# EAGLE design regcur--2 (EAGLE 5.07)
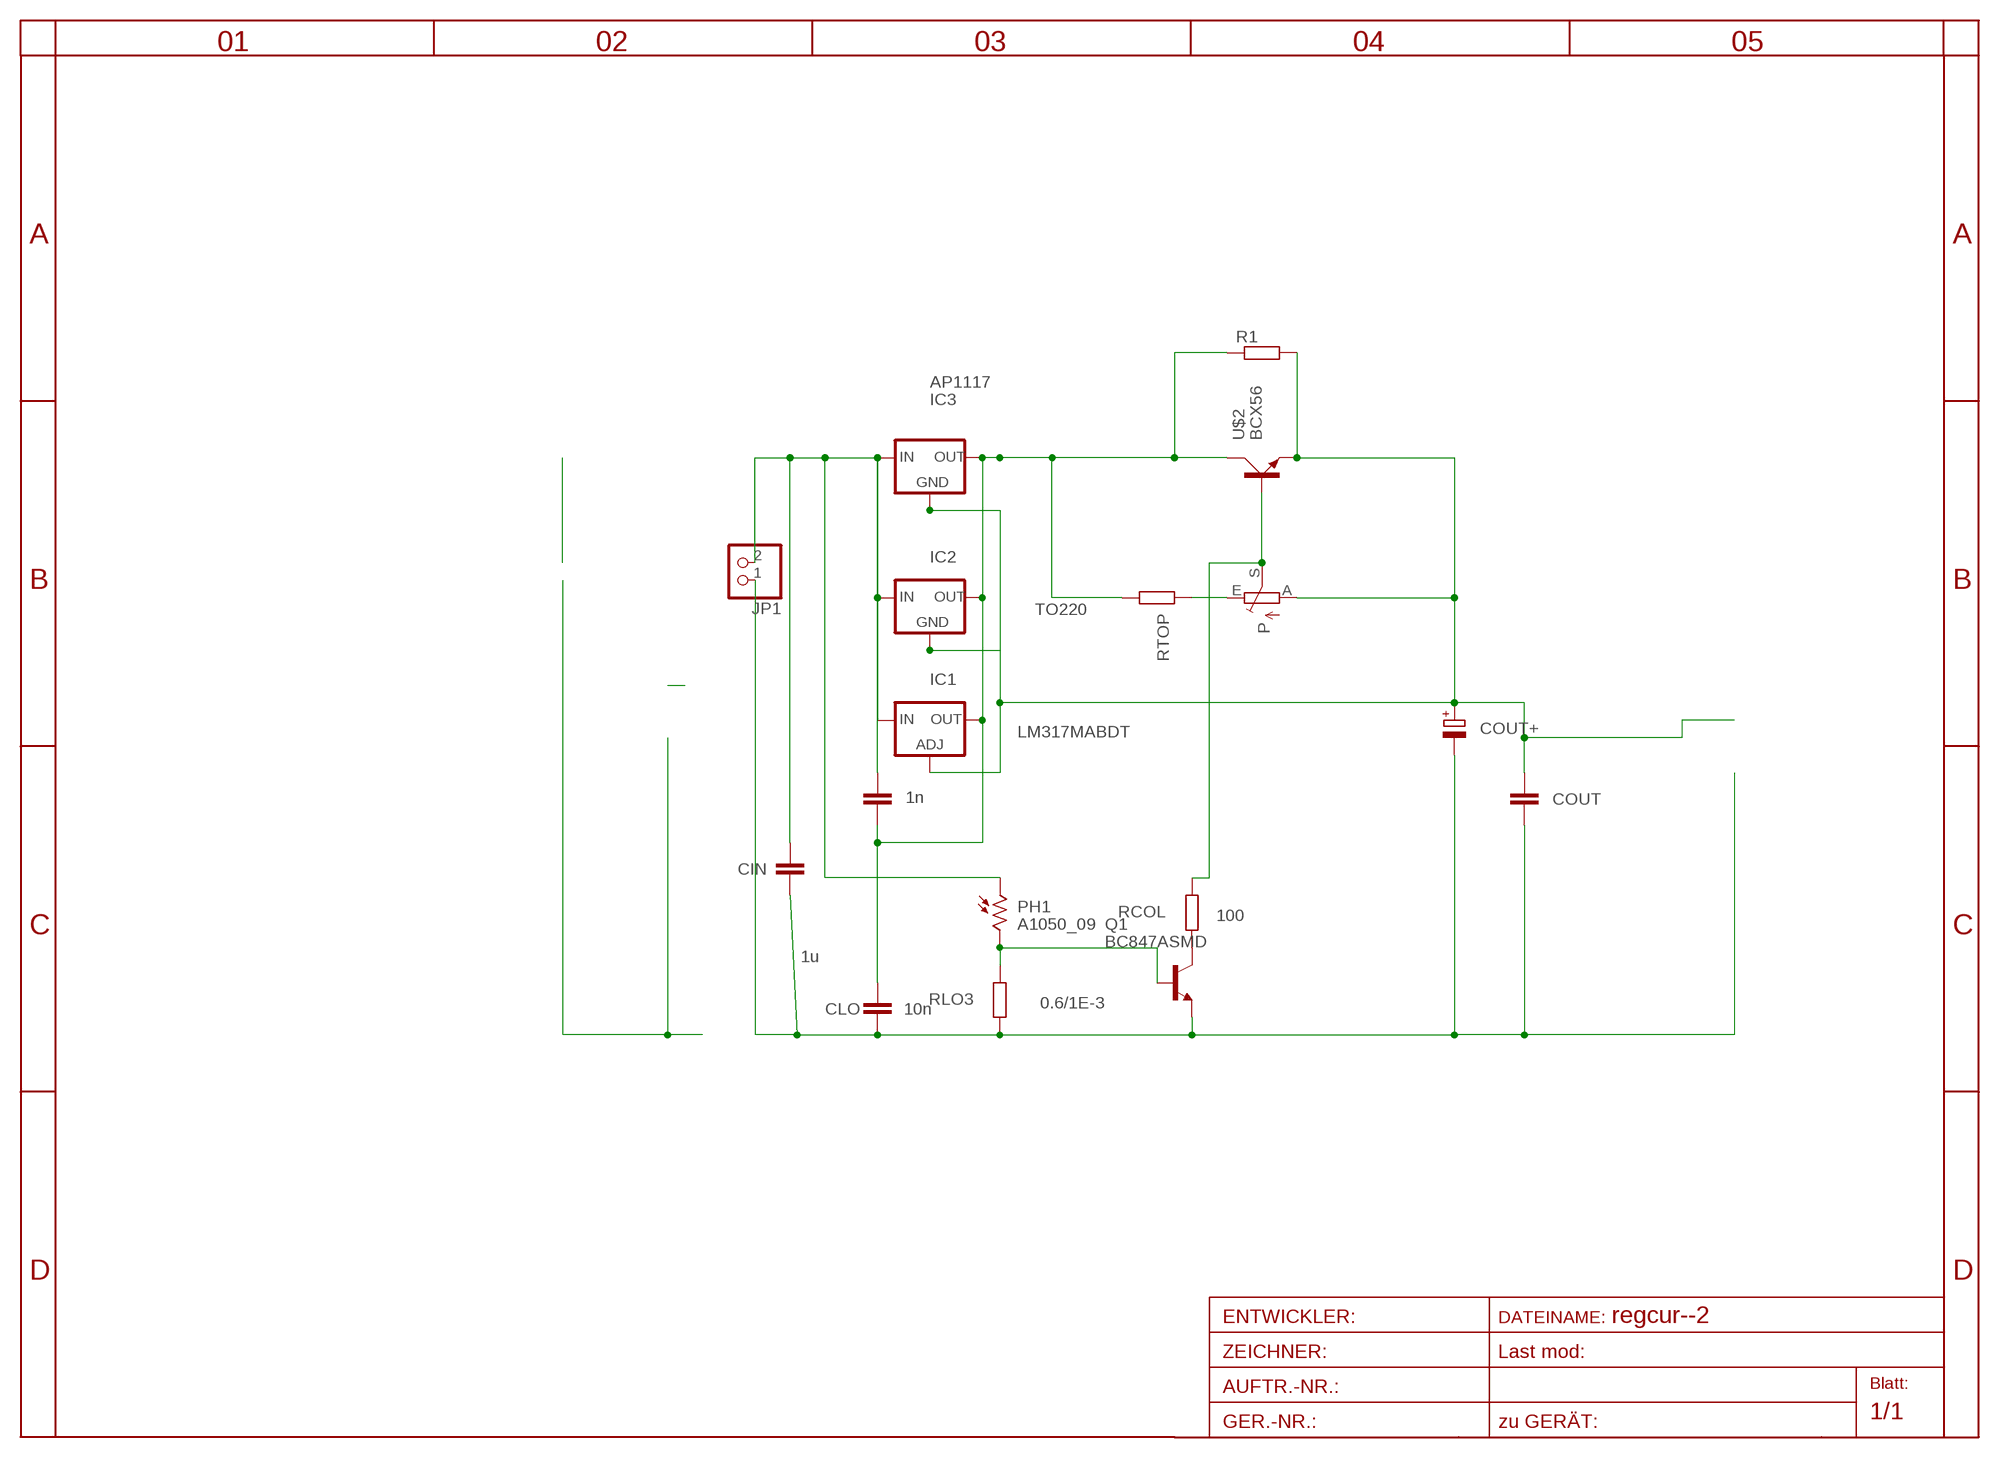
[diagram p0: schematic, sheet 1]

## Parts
CHI  1n  C-EUC0805  [C0805]
CIN  1u  C-EUC1206  [C1206]
CLO  10n  C-EUC0805  [C0805]
COUT  C-EUC1206  [C1206]
COUT+  CPOL-EUE7.5-16  [E7,5-16]
IC1  LM317MABDT  [DPACK]
IC2  TO220  78XXS  [78XXS]
IC3  AP1117  [SOT223]
JP1  PINHD-1X2STR  [1X02]
P  TRIM_EU-RAND160  [RANDL]
PH1  A1050_09  [T0-46-A10XX]
Q1  BC847ASMD  [SOT23]
R1  R-EU_R1210  [R1210]
RCOL  100  R-EU_R0805  [R0805]
RLO3  0.6/1E-3  R-EU_R0805  [R0805]
RTOP  R-EU_R0805  [R0805]
U$2  BCX56  [SOT223]

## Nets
GND: CIN.2 CLO.2 COUT+.- COUT.2 JP1.1 Q1.2(E) RLO3.1
IN: CHI.1 CIN.1 IC1.3(IN) IC2.IN IC3.3(IN) JP1.2 PH1.1
N$3: Q1.3(C) RCOL.1
N$4: P.E RTOP.1
N$5: P.S RCOL.2 U$2.1(B)
N$6: PH1.2 Q1.1(B) RLO3.2
OUT: COUT+.+ COUT.1 IC1.1(ADJ) IC2.GND IC3.1(GND) P.A R1.2 U$2.3(E)
OUT1: CHI.2 CLO.1 IC1.4(OUT) IC2.OUT IC3.2(OUT) IC3.4(TAB) R1.1 RTOP.2 U$2.2(C)

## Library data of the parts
CHI CIN CLO COUT = rcl:C-EU: CAPACITOR, European symbol
COUT+ = rcl:CPOL-EU: POLARIZED CAPACITOR, European symbol
IC1 = v-reg:LM317?*: 500 mA Adjustable Output Positive Voltage Regulator Source: http://www.onsemi.co.jp .. LM317M-D.PDF
IC2 = v-reg:78XXS: VOLTAGE REGULATOR
IC3 = v-reg:AP1117
JP1 = pinhead:PINHD-1X2: PIN HEADER
P = pot:TRIM_EU-: POTENTIOMETER
PH1 = photo-elements:A10: Sensor Robust Light Sensing Applications
Q1 = transistor-npn:BC847*: NPN Transistor
R1 RCOL RLO3 RTOP = rcl:R-EU_: RESISTOR, European symbol
U$2 = transistor-power:BCX56

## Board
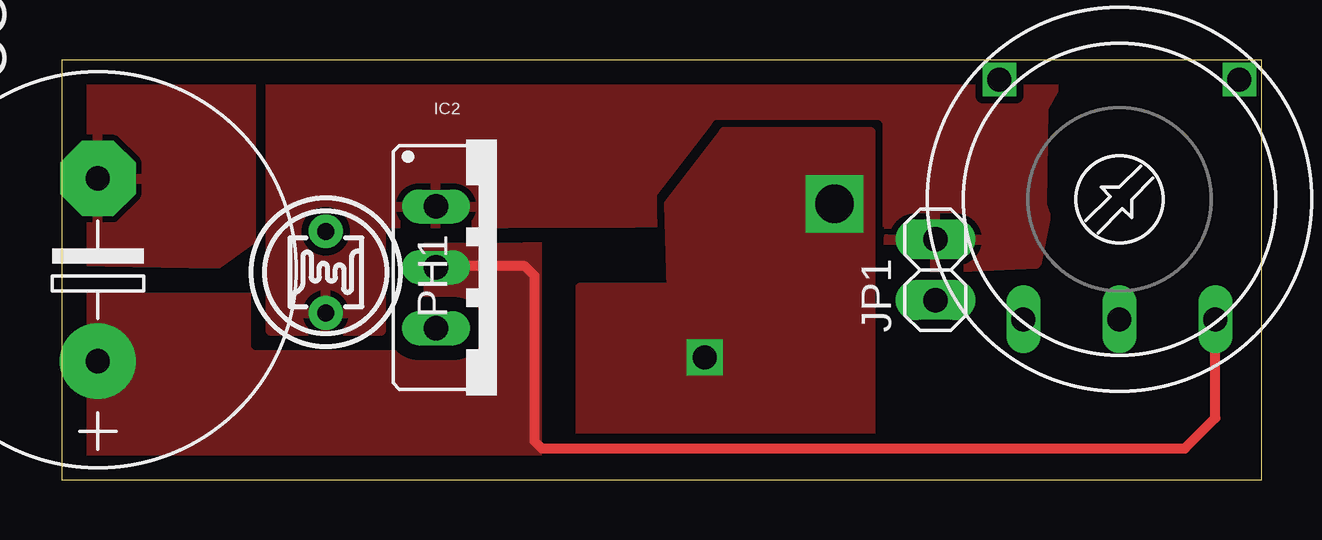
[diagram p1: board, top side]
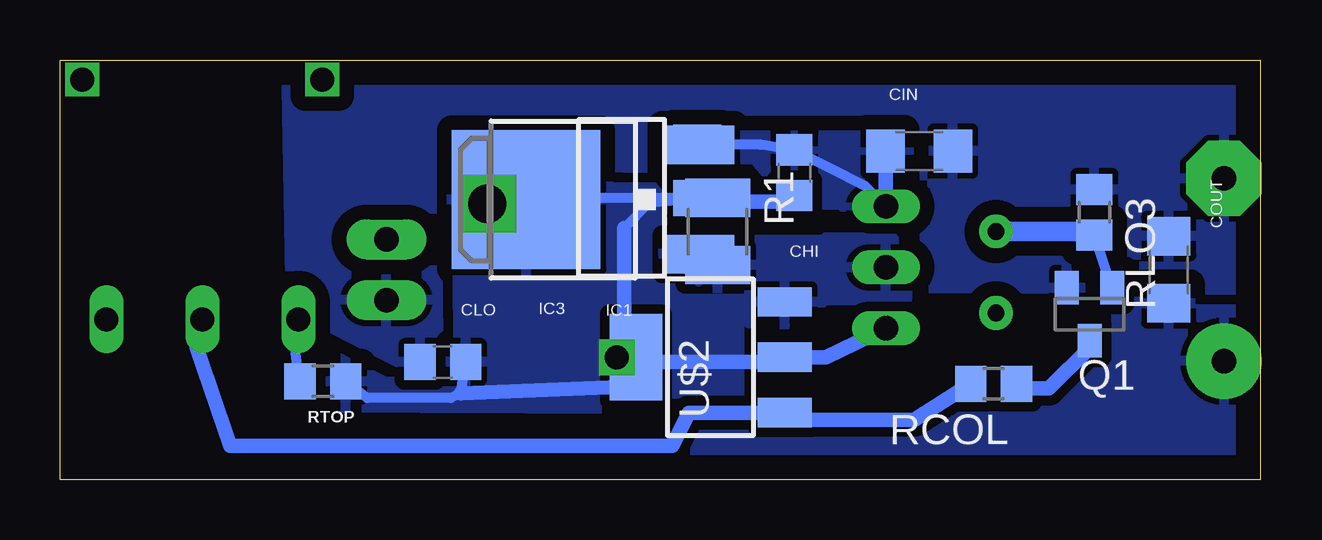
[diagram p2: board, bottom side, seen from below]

Size 50 x 17.5 mm. Coordinates in mm from the lower left corner, seen from the top.
Outline: 0,0 50,0 50,17.5 0,17.5 0,0
Copper layers (1*16): Top 0.035mm / dielectric 1.5mm / Bottom 0.035mm
Design rules "default *": minimum track width 10mil, minimum drill 20mil, track to track 8mil, track to pad 8mil, pad to pad 8mil, via to via 8mil, smd to smd 8mil, copper to edge 40mil, drill to drill 8mil, minimum pad ring 8mil, minimum via ring 8mil, stop-mask expansion 8mil, vias tented up to drill 0mil, thermal gap 10mil

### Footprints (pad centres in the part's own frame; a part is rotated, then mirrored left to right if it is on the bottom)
C0805 = smd 1.3 x 1.5: 1 -0.95,0; 2 0.95,0
C1206 = smd 1.6 x 1.8: 1 -1.4,0; 2 1.4,0
E7,5-16 = drill 1.016 pad 3.15 round: + -3.81,0 | drill 1.016 pad 3.15 octagon: - 3.81,0
DPACK = smd 1.6 x 3: 1 -2.28,-4.8; 3 2.28,-4.8 | smd 5.8 x 6.2: 4 0,2.38
78XXS = drill 1.016 long: GND 0,-2.54; IN -2.54,-2.54; OUT 2.54,-2.54
SOT223 = smd 1.5 x 2: 1 -2.3,-3.15; 2 0,-3.15; 3 2.3,-3.15 | smd 3.8 x 2: 4 0,3.15
1X02 = drill 1.016 pad 1.676 long: 1 -1.27,0; 2 1.27,0
RANDL = drill 1 long: A -4,5; E 4,5; S 0,5 | drill 1 square: P$1 -5,-5; P$2 5,-5
T0-46-A10XX = drill 0.7 pad 1.4 round: 1 -1.7,0; 2 1.7,0
SOT23 = smd 1 x 1.4: 1 -0.95,-1.1; 2 0.95,-1.1; 3 0,1.1
R1210 = smd 1.6 x 2.7: 1 -1.4,0; 2 1.4,0
R0805 = smd 1.3 x 1.5: 1 -0.95,0; 2 0.95,0
SOT223' = smd 1.219 x 2.235: 1 -2.311,-3.099; 2 0,-3.099; 3 2.311,-3.099 | smd 3.6 x 2.2: 4 0,3.099

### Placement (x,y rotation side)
CHI  19.4,12.8 270 bottom
CIN  14.2,13.7 0 bottom
CLO  34.05,4.9 180 bottom
COUT  3.8,8.75 90 bottom
COUT+  1.5,8.75 90 top
IC1  28.2,11.68 90 bottom
IC2  18.13,8.85 270 top
IC3  26.6,11.75 90 bottom
JP1  36.4,8.75 90 top
P  44.07,11.68 180 top
PH1  11,8.65 90 top
Q1  7.1,6.9 180 bottom
R1  22.6,10.35 270 bottom
RCOL  11.1,4 180 bottom
RLO3  6.9,11.15 270 bottom
RTOP  39.05,4.1 0 bottom
U$2  BCX56  [SOT223']  22.9,5.1 90 bottom

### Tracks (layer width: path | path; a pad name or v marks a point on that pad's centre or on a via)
GND
  pour Bottom (isolate 0.61, rank 2): 0.5,15 0.5,17.5 40.6,17.6 40.4,7.2 34.2,4 34.3,13.1 24.6,13 21.5,13.55 20.5,13.5 15.8,13.5 13.9,12.2 13.9,11.2 14,10.5 14.4,8 0.4,7.9
  pour Top (isolate 0.406, rank 3): 1,13.5 1,16.6 7.9,16.6 7.9,10 6.5,9 0.6,9.1
IN
  Bottom 0.406: IC1.3 20.81,13.96 CHI.1 16.45,12.25 IC2.IN
  Bottom 0.61: CIN.1 IC2.IN
  pour Top (isolate 0.305, rank 2): 41.5,16.57 40.9,15.5 40.84,11.5 41,11 40.6,9 34.4,8.7 34.5,10.75 13.3,10.65 13.3,6.2 8.7,6.2 8.7,16.5
  pour Bottom (isolate 0.406): 15.1,14.4 24.7,14.4 24.7,13.3 21.1,13.3 19.5,11.4 17.5,11.4 17.1,11 14.5,10.9 14.6,14.2
N$3
  Bottom 0.406: Q1.3 7.1,5.5 | 9.95,3.8 RCOL.1
  Bottom 0.61: 7.1,5.5 8.8,3.8 9.95,3.8
N$4
  Bottom 0.406: P.E 40.22,5.58 40.1,4.6 40.2,4.1 RTOP.1
N$5
  Bottom 0.406: 19.51,2.5 U$2.1 | 44.3,5.5 44.3,6.45 P.S
  Bottom 0.61: RCOL.2 14.4,2.5 19.51,2.5 | U$2.1 23.81,2.79 24.5,1.4 42.9,1.4 44.3,5.5
N$6
  Bottom 0.406: 7.45,10.35 RLO3.2 6.2,8.05 Q1.1
  Bottom 0.813: 7.45,10.35 PH1.2
OUT
  Top 0.406: P.A 48.07,2.57 46.8,1.3 20,1.3 19.7,1.6 19.7,8.5 19.3,8.9 15.64,8.9 IC2.GND
  Bottom 0.61: R1.2 23.1,9.4 IC1.1 IC3.1
  pour Bottom (isolate 0.406, rank 3): 33.7,6.2 33.5,4.2 33.3,0.5 0.3,0.5 0.3,7.4 6.6,7.4 6.5,6.2
  pour Top (isolate 0.61, rank 4, no thermals): 19.8,0 0,0 0,1.5 0.1,7.6 15.3,7.6 15.3,10.4 19.8,10.4
  pour Bottom (isolate 0.406, rank 3): 14.5,9.3 15.3,10.1 18.1,10.1 18.2,10 24,10 24.9,9.9 24.8,8.1 24.7,8 21.4,8 21.3,7.7 21.3,6.5 19.1,6.5 18.1,7.5 14.7,7.5
OUT1  (via drill 1, 1.6)
  Bottom 0.406: IC3.2 IC3.4 | IC3.2 25.45,11.55 26.5,10.5 | 25.8,4.9 26,5.1 | 26,5.1 26.35,5.45 26.5,5.6 | U$2.2 20,4.9 | 20.2,11.6 CHI.2 | 21.5,11.6 23.4,11.6 IC3.2 | RTOP.2 37.2,3.4 33.7,3.4 33.3,3.6 CLO.1 | 26,5.1 25.6,3.9
  Bottom 0.61: U$2.2 18.1,5.1 IC2.OUT | 26.5,5.6 26.5,10.5 | 20,4.9 25.8,4.9 | 21.5,11.6 20.2,11.6 | 25.6,3.9 33.3,3.6 | 23.4,11.6 22.7,11.6 R1.1 | v26.8,5.1 26.7,5.1 26.35,5.45
  other vias: 32.2,11.5
  pour Top (isolate 0.406): 21.6,8 21.6,1.9 33.7,1.9 33.7,14.5 27.6,14.5 25.3,11.5 25.4,8
  pour Bottom (isolate 0.406, rank 3): 21.7,8 21.7,2.9 39.4,3 33.6,14.5 26.9,14.2 24.5,11.2 24.6,8

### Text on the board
tStop: MICHAEL5.net
bStop: MICHAEL5.net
